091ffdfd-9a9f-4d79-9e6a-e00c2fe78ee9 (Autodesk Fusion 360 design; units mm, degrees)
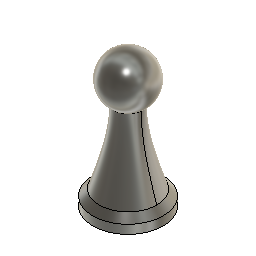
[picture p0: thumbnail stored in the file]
sketch "Sketch1" plane through (0, 0, 0) normal (0, 1, 0) x axis (1, 0, 0)
  line L1 (0, -35) -> (0, 0)
  line L2 (10, 0) -> (0, 0)
  line L3 (10, -2.5) -> (10, 0)
  line L4 (8.2121, -4.2933) -> (10, -2.5)
  curve K1 (3.8172, -25.535) -> (8.2121, -4.2933)
  line L5 (0, -38.4821) -> (0, -35)
  arc A1 centre (0, -31.3948) radius 7.0873 clockwise from (3.8146, -25.4216) to (0, -38.4821)
  point P1 (0, 0)
  point P2 (0, 0)
  point P4 (0, 0)
  point P10 (0, -31.3948)
  point P12 (3.8146, -25.4216)
  point P3 (0, -35)
  point P5 (10, 0)
  point P6 (10, -2.5)
  coincident P1 P2
  vertical L1
  coincident P1 P4
  perpendicular L1 L2
  perpendicular L2 L3
  coincident L1 P10
  parallel L1 L5
  coincident K1 P12
  dimension "d1" distance P2 P3 = 35
  dimension "d2" distance P4 P5 = 10
  dimension "d3" distance P5 P6 = 2.5
revolve "Revolve1" sketch "Sketch1" AlongAngle 360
